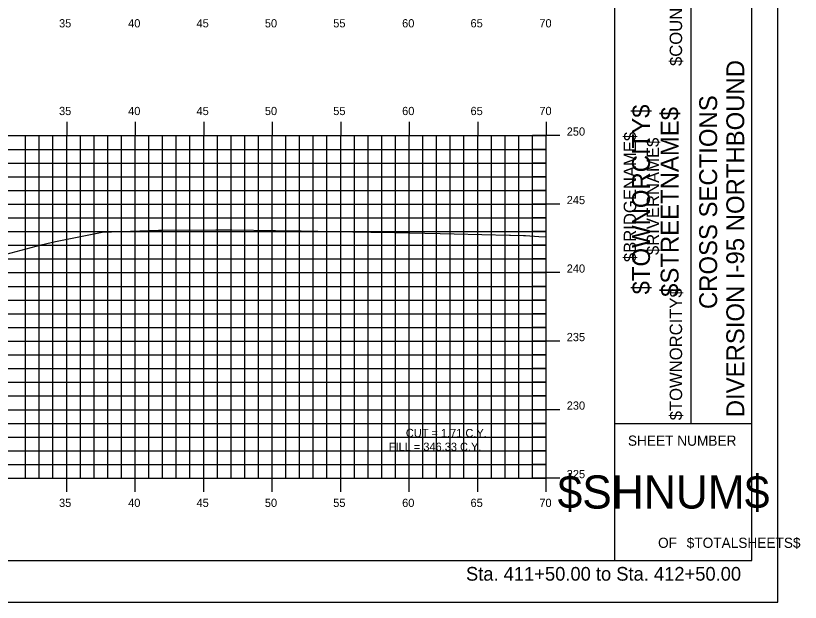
# Model space of a CAD drawing. Extents: x 1160718 to 1173142, y 616002 to 617630.
# Drawn here: x 1167997.9 to 1168055.1, y 616613.9 to 616656.7 of the extents above; entities that cross this region are included whole.
import ezdxf

# ---------------------------------------------------------------- set-up
doc = ezdxf.new("R2010")
doc.units = 0
for name, color, linetype in [('ANNOTATION', 7, 'Continuous'), ('BORDER', 7, 'Continuous'), ('BRIDGE_TITLE', 7, 'Continuous'), ('H_V ANNOTATION', 7, 'Continuous'), ('HIGHWAY_TITLE', 7, 'Continuous'), ('MAJOR', 7, 'Continuous'), ('MINOR', 7, 'Continuous'), ('PLOT BOUNDARY', 7, 'Continuous'), ('S_Roadway_Centerline', 7, 'Continuous')]:
    doc.layers.add(name, color=color, linetype=linetype)

msp = doc.modelspace()

# ---------------------------------------------------------------- linework, layer by layer
at = {"layer": 'BORDER'}
for p, q in [((1168041.585, 616616.931), (1168041.585, 616721.931)), ((1168051.585, 616616.931), (1168051.585, 616721.931)), ((1168047.176, 616626.931), (1168047.176, 616661.931)), ((1168041.585, 616626.931), (1168051.585, 616626.931)), ((1167891.585, 616616.928), (1168051.585, 616616.928))]:
    msp.add_line(p, q, dxfattribs=at)
at = {"layer": 'MAJOR'}
for p, q in [((1168001.585, 616648.93), (1168001.585, 616647.928)), ((1168006.585, 616648.93), (1168006.585, 616647.928)), ((1168011.585, 616648.93), (1168011.585, 616647.928)), ((1168016.585, 616648.93), (1168016.585, 616647.928)), ((1168021.585, 616648.93), (1168021.585, 616647.928)), ((1168026.585, 616648.93), (1168026.585, 616647.928)), ((1168031.585, 616648.93), (1168031.585, 616647.928)), ((1168036.585, 616648.93), (1168036.585, 616647.928)), ((1167896.585, 616647.928), (1168036.585, 616647.928)), ((1167896.585, 616647.928), (1168036.585, 616647.928)), ((1168001.585, 616622.928), (1168001.585, 616647.928)), ((1168006.585, 616622.928), (1168006.585, 616647.928)), ((1168011.585, 616622.928), (1168011.585, 616647.928)), ((1168016.585, 616622.928), (1168016.585, 616647.928)), ((1168021.585, 616622.928), (1168021.585, 616647.928)), ((1168026.585, 616622.928), (1168026.585, 616647.928)), ((1168031.585, 616622.928), (1168031.585, 616647.928)), ((1168037.587, 616647.928), (1168035.583, 616647.928)), ((1168036.585, 616622.928), (1168036.585, 616647.928)), ((1168036.585, 616622.928), (1168036.585, 616647.928)), ((1167896.585, 616642.928), (1168036.585, 616642.928)), ((1168037.587, 616642.928), (1168035.583, 616642.928)), ((1167896.585, 616637.928), (1168036.585, 616637.928)), ((1168037.587, 616637.928), (1168035.583, 616637.928)), ((1167896.585, 616632.928), (1168036.585, 616632.928)), ((1168037.587, 616632.928), (1168035.583, 616632.928)), ((1167896.585, 616627.928), (1168036.585, 616627.928)), ((1168037.587, 616627.928), (1168035.583, 616627.928)), ((1167896.585, 616622.928), (1168036.585, 616622.928)), ((1167896.585, 616622.928), (1168036.585, 616622.928)), ((1168001.585, 616621.926), (1168001.585, 616622.928)), ((1168006.585, 616621.926), (1168006.585, 616622.928)), ((1168011.585, 616621.926), (1168011.585, 616622.928)), ((1168016.585, 616621.926), (1168016.585, 616622.928)), ((1168021.585, 616621.926), (1168021.585, 616622.928)), ((1168026.585, 616621.926), (1168026.585, 616622.928)), ((1168031.585, 616621.926), (1168031.585, 616622.928)), ((1168037.587, 616622.928), (1168035.583, 616622.928)), ((1168036.585, 616621.926), (1168036.585, 616622.928))]:
    msp.add_line(p, q, dxfattribs=at)
at = {"layer": 'MINOR'}
for p, q in [((1167998.585, 616622.928), (1167998.585, 616647.928)), ((1167999.585, 616622.928), (1167999.585, 616647.928)), ((1168000.585, 616622.928), (1168000.585, 616647.928)), ((1168002.585, 616622.928), (1168002.585, 616647.928)), ((1168003.585, 616622.928), (1168003.585, 616647.928)), ((1168004.585, 616622.928), (1168004.585, 616647.928)), ((1168005.585, 616622.928), (1168005.585, 616647.928)), ((1168007.585, 616622.928), (1168007.585, 616647.928)), ((1168008.585, 616622.928), (1168008.585, 616647.928)), ((1168009.585, 616622.928), (1168009.585, 616647.928)), ((1168010.585, 616622.928), (1168010.585, 616647.928)), ((1168012.585, 616622.928), (1168012.585, 616647.928)), ((1168013.585, 616622.928), (1168013.585, 616647.928)), ((1168014.585, 616622.928), (1168014.585, 616647.928)), ((1168015.585, 616622.928), (1168015.585, 616647.928)), ((1168017.585, 616622.928), (1168017.585, 616647.928)), ((1168018.585, 616622.928), (1168018.585, 616647.928)), ((1168019.585, 616622.928), (1168019.585, 616647.928)), ((1168020.585, 616622.928), (1168020.585, 616647.928)), ((1168022.585, 616622.928), (1168022.585, 616647.928)), ((1168023.585, 616622.928), (1168023.585, 616647.928)), ((1168024.585, 616622.928), (1168024.585, 616647.928)), ((1168025.585, 616622.928), (1168025.585, 616647.928)), ((1168027.585, 616622.928), (1168027.585, 616647.928)), ((1168028.585, 616622.928), (1168028.585, 616647.928)), ((1168029.585, 616622.928), (1168029.585, 616647.928)), ((1168030.585, 616622.928), (1168030.585, 616647.928)), ((1168032.585, 616622.928), (1168032.585, 616647.928)), ((1168033.585, 616622.928), (1168033.585, 616647.928)), ((1168034.585, 616622.928), (1168034.585, 616647.928)), ((1168035.585, 616622.928), (1168035.585, 616647.928)), ((1167896.585, 616646.928), (1168036.585, 616646.928)), ((1168036.585, 616646.928), (1168035.583, 616646.928)), ((1167896.585, 616645.928), (1168036.585, 616645.928)), ((1168036.585, 616645.928), (1168035.583, 616645.928)), ((1167896.585, 616644.928), (1168036.585, 616644.928)), ((1168036.585, 616644.928), (1168035.583, 616644.928)), ((1167896.585, 616643.928), (1168036.585, 616643.928)), ((1168036.585, 616643.928), (1168035.583, 616643.928)), ((1167896.585, 616641.928), (1168036.585, 616641.928)), ((1168036.585, 616641.928), (1168035.583, 616641.928)), ((1167896.585, 616640.928), (1168036.585, 616640.928)), ((1168036.585, 616640.928), (1168035.583, 616640.928)), ((1167896.585, 616639.928), (1168036.585, 616639.928)), ((1168036.585, 616639.928), (1168035.583, 616639.928)), ((1167896.585, 616638.928), (1168036.585, 616638.928)), ((1168036.585, 616638.928), (1168035.583, 616638.928)), ((1167896.585, 616636.928), (1168036.585, 616636.928)), ((1168036.585, 616636.928), (1168035.583, 616636.928)), ((1167896.585, 616635.928), (1168036.585, 616635.928)), ((1168036.585, 616635.928), (1168035.583, 616635.928)), ((1167896.585, 616634.928), (1168036.585, 616634.928)), ((1168036.585, 616634.928), (1168035.583, 616634.928)), ((1167896.585, 616633.928), (1168036.585, 616633.928)), ((1168036.585, 616633.928), (1168035.583, 616633.928)), ((1167896.585, 616631.928), (1168036.585, 616631.928)), ((1168036.585, 616631.928), (1168035.583, 616631.928)), ((1167896.585, 616630.928), (1168036.585, 616630.928)), ((1168036.585, 616630.928), (1168035.583, 616630.928)), ((1167896.585, 616629.928), (1168036.585, 616629.928)), ((1168036.585, 616629.928), (1168035.583, 616629.928)), ((1167896.585, 616628.928), (1168036.585, 616628.928)), ((1168036.585, 616628.928), (1168035.583, 616628.928)), ((1167896.585, 616626.928), (1168036.585, 616626.928)), ((1168036.585, 616626.928), (1168035.583, 616626.928)), ((1167896.585, 616625.928), (1168036.585, 616625.928)), ((1168036.585, 616625.928), (1168035.583, 616625.928)), ((1167896.585, 616624.928), (1168036.585, 616624.928)), ((1168036.585, 616624.928), (1168035.583, 616624.928)), ((1167896.585, 616623.928), (1168036.585, 616623.928)), ((1168036.585, 616623.928), (1168035.583, 616623.928))]:
    msp.add_line(p, q, dxfattribs=at)
at = {"layer": 'PLOT BOUNDARY'}
msp.add_lwpolyline([(1167883.492, 616613.869), (1168053.492, 616613.869), (1168053.492, 616723.869), (1167883.492, 616723.869)], close=True, dxfattribs=at)
at = {"layer": 'S_Roadway_Centerline'}
msp.add_lwpolyline([(1167996.409, 616639.082), (1167999.721, 616639.969), (1168000.459, 616640.139), (1168000.78, 616640.209), (1168002.599, 616640.562), (1168004.187, 616640.883), (1168008.284, 616641.031), (1168008.573, 616641.04), (1168012.466, 616641.046), (1168013.641, 616641.047), (1168016.816, 616640.999), (1168018.709, 616640.969), (1168021.166, 616640.93), (1168023.777, 616640.887), (1168025.515, 616640.851), (1168028.845, 616640.781), (1168029.865, 616640.758), (1168033.912, 616640.67), (1168033.975, 616640.668), (1168034.931, 616640.642), (1168035.064, 616640.634), (1168036.051, 616640.572), (1168036.585, 616640.538)], dxfattribs=at)

# ---------------------------------------------------------------- texts
at = {"layer": 'ANNOTATION'}
for s, p in [('CUT = 1.71 C.Y.', (1168026.341, 616625.927)), ('FILL = 346.33 C.Y.', (1168025.098, 616624.926))]:
    msp.add_text(s, height=0.6, rotation=359.9241, dxfattribs=at).set_placement(p)
at = {"layer": 'BORDER'}
for s, height, rotation, p in [('DIVERSION I-95 NORTHBOUND  ', 1.30428, 90, (1168051.039, 616627.379)), ('CROSS SECTIONS', 1.30428, 90, (1168049.061, 616635.27)), ('SHEET NUMBER', 0.74527, 360, (1168042.551, 616625.295)), ('$SHNUM$', 2.4194, 360, (1168037.418, 616620.711)), ('$TOTALSHEETS$', 0.74527, 360, (1168046.842, 616617.841)), ('OF', 0.7453, 360, (1168044.752, 616617.841))]:
    msp.add_text(s, height=height, rotation=rotation, dxfattribs=at).set_placement(p)
at = {"layer": 'BRIDGE_TITLE'}
for s, height, p in [('$COUNTY$', 0.9072, (1168046.505, 616653.011)), ('$BRIDGENAME$', 0.90716, (1168043.151, 616638.7)), ('$RIVERNAME$', 0.90716, (1168044.828, 616639.214)), ('$TOWNORCITY$', 0.90716, (1168046.505, 616627.152))]:
    msp.add_text(s, height=height, rotation=90, dxfattribs=at).set_placement(p)
at = {"layer": 'H_V ANNOTATION'}
for s, height, p in [('35', 0.6, (1168001.026, 616655.828)), ('40', 0.6, (1168006.071, 616655.828)), ('45', 0.6, (1168011.063, 616655.828)), ('50', 0.6, (1168016.05, 616655.828)), ('55', 0.6, (1168021.042, 616655.828)), ('60', 0.6, (1168026.071, 616655.828)), ('65', 0.6, (1168031.063, 616655.828)), ('70', 0.6, (1168036.087, 616655.828)), ('35', 0.6, (1168001.026, 616649.428)), ('40', 0.6, (1168006.071, 616649.428)), ('45', 0.6, (1168011.063, 616649.428)), ('50', 0.6, (1168016.05, 616649.428)), ('55', 0.6, (1168021.042, 616649.428)), ('60', 0.6, (1168026.071, 616649.428)), ('65', 0.6, (1168031.063, 616649.428)), ('70', 0.6, (1168036.087, 616649.428)), ('250', 0.6, (1168038.085, 616647.928)), ('245', 0.6, (1168038.085, 616642.928)), ('240', 0.6, (1168038.085, 616637.928)), ('235', 0.6, (1168038.085, 616632.928)), ('230', 0.6, (1168038.085, 616627.928)), ('225', 0.6, (1168038.085, 616622.928)), ('35', 0.6, (1168001.026, 616620.828)), ('40', 0.6, (1168006.071, 616620.828)), ('45', 0.6, (1168011.063, 616620.828)), ('50', 0.6, (1168016.05, 616620.828)), ('55', 0.6, (1168021.042, 616620.828)), ('60', 0.6, (1168026.071, 616620.828)), ('65', 0.6, (1168031.063, 616620.828)), ('70', 0.6, (1168036.087, 616620.828)), ('Sta. 411+50.00 to Sta. 412+50.00', 1.0002, (1168030.731, 616615.448))]:
    msp.add_text(s, height=height, dxfattribs=at).set_placement(p)
at = {"layer": 'HIGHWAY_TITLE'}
for s, p in [('$TOWNORCITY$', (1168044.158, 616636.34)), ('$STREETNAME$', (1168046.245, 616636.16))]:
    msp.add_text(s, height=1.30428, rotation=90, dxfattribs=at).set_placement(p)

doc.saveas('drawing.dxf')
